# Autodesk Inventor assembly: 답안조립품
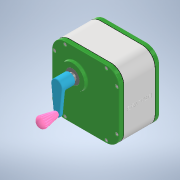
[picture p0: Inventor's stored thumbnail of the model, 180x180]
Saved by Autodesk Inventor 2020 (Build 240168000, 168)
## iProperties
Created: 2022-03
Part Number: 답안조립품
Document SubType Name: Assembly
Designer: Administrator
Mass: 4441.38 g
Surface Area: 3085.81 cm^2
Volume: 1260.3 cm^3
Density: 3.52406 g/cm^3
Author: Administrator
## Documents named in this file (14)
- C:\Users\Administrator\Desktop\620306V1022\답안조립품.iam
- C:\Users\Administrator\Desktop\620306V1022\공용부품\개스킷.ipt
- C:\Users\Administrator\Desktop\620306V1022\공용부품\뒤커버.ipt
- C:\Users\Administrator\Desktop\620306V1022\공용부품\메인축.ipt
- C:\Users\Administrator\Desktop\620306V1022\공용부품\베어링 608.ipt
- C:\Users\Administrator\Desktop\620306V1022\공용부품\베어링 6003.ipt
- C:\Users\Administrator\Desktop\620306V1022\공용부품\본체.ipt
- C:\Users\Administrator\Desktop\620306V1022\공용부품\볼트 M4.ipt
- C:\Users\Administrator\Desktop\620306V1022\공용부품\서브축.ipt
- C:\Users\Administrator\Desktop\620306V1022\공용부품\손잡이A.ipt
- C:\Users\Administrator\Desktop\620306V1022\공용부품\손잡이B.ipt
- C:\Users\Administrator\Desktop\620306V1022\공용부품\앞커버.ipt
- C:\Users\Administrator\Desktop\620306V1022\공용부품\오일실 8 x 22 x 7.ipt
- C:\Users\Administrator\Desktop\620306V1022\공용부품\오일실 17 x 32 x 8.ipt
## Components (2 placed, 1 different names)
1. 개스킷:1
2. 개스킷:2
